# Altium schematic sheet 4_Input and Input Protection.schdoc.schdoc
size 309 x 223 mm; Symbol: Sheet-Symbol-Custom; Device: Sheet-Symbol-Custom; @Page Count: 4; @Create Date: 2024-03-28; Drawn: Thomas Crisafulli; @Page No: 1; @Page Name: Input and Input Protection; @Project Name: OhmmeterV1.1_Release; @Schematic Name: Schematic 1; Page Size: A4; @Update Date: 2024-03-27
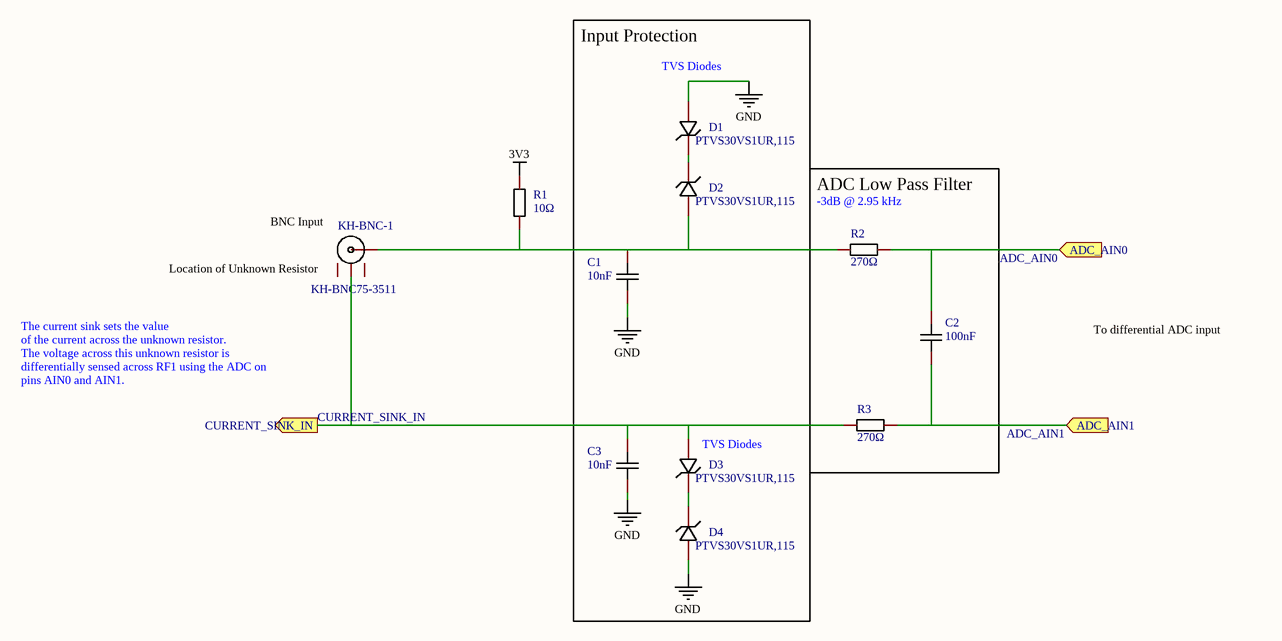
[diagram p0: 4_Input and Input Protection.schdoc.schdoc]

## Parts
C1  10nF  [C0603]
C2  100nF  [C0603]
C3  10nF  [C0603]
D1  PTVS30VS1UR,115  [SOD-123_L2.6-W1.7-LS3.5-RD]
D2  PTVS30VS1UR,115  [SOD-123_L2.6-W1.7-LS3.5-RD]
D3  PTVS30VS1UR,115  [SOD-123_L2.6-W1.7-LS3.5-RD]
D4  PTVS30VS1UR,115  [SOD-123_L2.6-W1.7-LS3.5-RD]
KH-BNC-1  KH-BNC75-3511  [ANT-TH_KH-BNC75-3511]
R1  10Ω  [R0603]
R2  270Ω  [R0603]
R3  270Ω  [R0603]

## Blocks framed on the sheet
Input Protection: C1 C3 D1-D4
ADC Low Pass Filter: C2 R2 R3

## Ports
ADC_AIN0 (in), ADC_AIN1 (in), CURRENT_SINK_IN (out)

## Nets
3V3: R1.2
GND: C1.2 C3.2 D1.2(A) D4.2(A)
ADC_AIN0: C2.2 R2.2 ; port ADC_AIN0
ADC_AIN1: C2.1 R3.2 ; port ADC_AIN1
CURRENT_SINK_IN: C3.1 D3.2(A) KH-BNC-1.2 R3.1 ; port CURRENT_SINK_IN
NetC1_1: C1.1 D2.2(A) KH-BNC-1.1(OUT) R1.1 R2.1
NetD1_1: D1.1(C) D2.1(C)
NetD3_1: D3.1(C) D4.1(C)

Not connected (* = marked no-connect by the designer): KH-BNC-1 3 4

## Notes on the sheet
- (near D1) TVS Diodes
- (near R2) -3dB @ 2.95 kHz
- (near KH-BNC-1) Location of Unknown Resistor
- (near KH-BNC-1) BNC Input
- The current sink sets the value
  of the current across the unknown resistor.
  The voltage across this unknown resistor is
  differentially sensed across RF1 using the ADC on
  pins AIN0 and AIN1.
- To differential ADC input
- (near D3) TVS Diodes

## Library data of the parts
C1 C3 = 06031C103K4T2A: Manufacturer: Kyocera AVX; Add into BOM: yes; Tolerance: ±10%; Description: Capacitance: Tolerance:±10% Tolerance:±10% Voltage Rated: Temperature Coefficient:
C2 = CC0603KRX7R9BB104: Manufacturer: YAGEO(国巨); Add into BOM: yes; Tolerance: ±10%; Description: Capacitance: Tolerance:±10% Tolerance:±10% Voltage Rated: Temperature Coefficient:
D1-D4 = PTVS30VS1UR,115: Polarity:- Reverse Stand-Off Voltage (Vrwm):30V Breakdown Voltage (Min):33.3V Breakdown Voltage (Max):36.8V Reverse Leakage Current (Ir):0.1uA Peak Pulse Current (Ipp)@10/1000s:- Maximum Clamping Voltage:48.4V Peak Pulse Power Dissipation (Ppp)@10/1000s; Manufacturer: Nexperia(安世); Add into BOM: yes; Reverse Stand-Off Voltage (Vrwm): 30V; Breakdown Voltage (Min): 33.3V; Breakdown Voltage (Max): 36.8V; Reverse Leakage Current (Ir): 0.1uA; Maximum Clamping Voltage: 48.4V; Peak Pulse Power Dissipation (Ppp)@10/1000μs: 400W
KH-BNC-1 = KH-BNC75-3511: Connector Type:板端 RF Series:BNC Interface Type:内孔 Number of Ports:1 Impedance:75Ω Frequency-Max:3GHz Style:弯头 Interface Diameter:9.5mm Interface Length/Height:- Operating Temperature Range:-55~+155 Operating Temperature Range:-55~+155; Manufacturer: kinghelm(金航标); Add into BOM: yes; Connector Type: 板端; RF Series: BNC; Interface Type: 内孔; Number of Ports: 1; Impedance: 75Ω; Frequency-Max: 3GHz; Style: 弯头; Interface Diameter: 9.5mm
R1 = AC0603FR-0710RL: Manufacturer: YAGEO(国巨); Add into BOM: yes; Tolerance: ±1%; Temperature Coefficient: ±200ppm/℃; Description: Type:Thick Film Resistors Resistance: Tolerance:±1% Tolerance:±1% Power(Watts): Overload Voltage (Max): Temperature Coefficient:±200ppm/℃ Temperature Coefficient:±200ppm/℃ Operating Temperature Range:-55℃~+155℃ Operating Temperature Range:-55℃~+155℃
R2 R3 = RS-03K2700FT: Resistance: Tolerance:±1% Tolerance:±1% Power(Watts): Temperature Coefficient:±100ppm/ Temperature Coefficient:±100ppm/ Overload Voltage (Max): Operating Temperature Range:-55~+155 Operating Temperature Range:-55~+155; Manufacturer: FH(风华); Add into BOM: yes; Tolerance: ±1%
